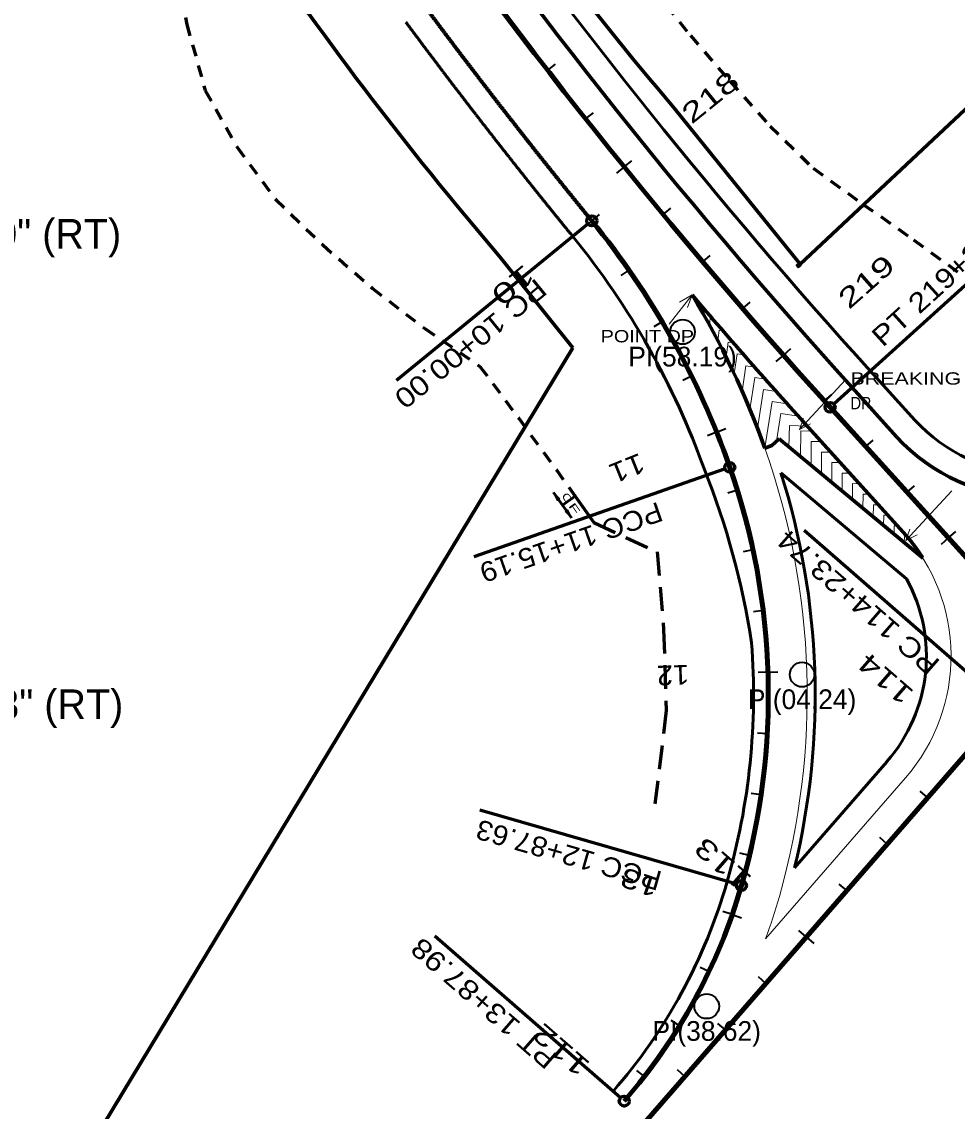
# Model space of a CAD drawing. Extents: x 2717836 to 2719883, y 337327 to 339813.
# Drawn here: x 2718674.4 to 2719054.1, y 337871.3 to 338313.3 of the extents above; entities that cross this region are included whole.
import ezdxf
from ezdxf.enums import TextEntityAlignment as Align

# ---------------------------------------------------------------- set-up
doc = ezdxf.new("R2010")
doc.units = 0
doc.header["$LTSCALE"] = 3.2
for name, pattern in [('LONG_DASHED', [7.5, 6, -1.5]), ('MEDIUM_DASHED', [4.5, 3, -1.5]), ('SHORT_DASHED', [2.7, 1.5, -1.2])]:
    doc.linetypes.add(name, pattern=pattern)
for name, color, linetype, lineweight in [('1', 7, 'Continuous', 106), ('2', 7, 'Continuous', 13), ('22', 7, 'SHORT_DASHED', 60), ('23', 7, 'Continuous', 70), ('24', 7, 'Continuous', 13), ('3', 7, 'Continuous', 70), ('31', 7, 'Continuous', 35), ('52', 7, 'Continuous', 53), ('6', 7, 'Continuous', 53), ('60', 7, 'Continuous', 13), ('61', 7, 'Continuous', 13), ('62', 7, 'Continuous', 13), ('8', 7, 'Continuous', 70)]:
    doc.layers.add(name, color=color, linetype=linetype, lineweight=lineweight)

msp = doc.modelspace()

# ---------------------------------------------------------------- hatches: boundary and pattern name
at = {"layer": '23'}
msp.add_hatch(color=256, dxfattribs=at).paths.add_polyline_path([(2718989.701, 338213.433), (2718988.659, 338214.512), (2718989.738, 338215.554), (2718990.78, 338214.474)])
at = {"layer": '52'}
for points in [[(2718890.257, 338122.283), (2718892.832, 338119.693), (2718891.815, 338120.076), (2718891.826, 338118.982)], [(2718897.478, 338112.08), (2718894.903, 338114.67), (2718895.92, 338114.288), (2718895.908, 338115.382)]]:
    msp.add_hatch(color=256, dxfattribs=at).paths.add_polyline_path(points)

# ---------------------------------------------------------------- linework, layer by layer
at = {"layer": '1'}
for p, q in [((2719002.473, 338156.897), (2719189.327, 337950.539)), ((2718598.813, 337489.479), (2719074.059, 338035.314))]:
    msp.add_line(p, q, dxfattribs=at)
for centre, radius, start, end in [((2720744.453, 339734.238), 2350, 206.79977, 222.16044), ((2718650.191, 338023.775), 330, 19.23982, 39.23982), ((2718697.399, 338040.251), 280, 343.95467, 19.23982), ((2718745.451, 338026.431), 230, 318.95467, 343.95467)]:
    msp.add_arc(centre, radius, start, end, dxfattribs=at)
at = {"layer": '2'}
msp.add_line((2719033.086, 338006.53), (2718976.223, 337941.221), dxfattribs=at)
for centre, radius, start, end in [((2718692.921, 338040.106), 300.266, 344.21749, 19.50264), ((2718976.549, 338055.909), 75, 318.86607, 42.16044), ((2718745.451, 338026.431), 246, 339.73408, 343.95467)]:
    msp.add_arc(centre, radius, start, end, dxfattribs=at)
at = {"layer": '22'}
for p, q in [((2718736.378, 338340.568), (2718741.398, 338312.243)), ((2718930.49, 338326.699), (2718945.807, 338307.673)), ((2718741.398, 338312.243), (2718748.912, 338285.405)), ((2718945.807, 338307.673), (2718961.775, 338289.179)), ((2718961.775, 338289.179), (2718978.102, 338271.004)), ((2718748.912, 338285.405), (2718761.889, 338262.366)), ((2718978.102, 338271.004), (2718995.614, 338253.858)), ((2718761.889, 338262.366), (2718777.485, 338241.226)), ((2718995.614, 338253.858), (2719015.923, 338239.196)), ((2718777.485, 338241.226), (2718796.55, 338222.768)), ((2718796.55, 338222.768), (2718816.646, 338205.231)), ((2718816.646, 338205.231), (2718837.975, 338188.825)), ((2718837.975, 338188.825), (2718860.375, 338173.479)), ((2718860.375, 338173.479), (2718875.971, 338152.581)), ((2718875.971, 338152.581), (2718891.404, 338131.497)), ((2718891.404, 338131.497), (2718898.972, 338120.794))]:
    msp.add_line(p, q, dxfattribs=at)
at = {"layer": '22', "linetype": 'LONG_DASHED'}
msp.add_line((2718898.972, 338120.794), (2718906.541, 338110.092), dxfattribs=at)
at = {"layer": '22', "linetype": 'MEDIUM_DASHED'}
msp.add_line((2718906.541, 338110.092), (2718932.305, 338098.2), dxfattribs=at)
at = {"layer": '22'}
msp.add_lwpolyline([(2719015.923, 338239.196), (2719036.374, 338224.824), (2719056.377, 338210.214)], dxfattribs=at)
at = {"layer": '22', "linetype": 'MEDIUM_DASHED'}
msp.add_lwpolyline([(2718932.305, 338098.2), (2718934.904, 338066.645), (2718935.99, 338033.903), (2718931.4, 337996.021)], dxfattribs=at)
at = {"layer": '23'}
for p, q in [((2719374.169, 338574.501), (2718990.259, 338215.014)), ((2718939.297, 338278.13), (2718990.259, 338215.014)), ((2718868.503, 338217.98), (2718898.006, 338180.983)), ((2718898.006, 338180.983), (2718492.996, 337510.896))]:
    msp.add_line(p, q, dxfattribs=at)
at = {"layer": '23', "lineweight": 25}
msp.add_lwpolyline([(2718989.701, 338213.433), (2718988.659, 338214.512), (2718989.738, 338215.554), (2718990.78, 338214.474)], close=True, dxfattribs=at)
at = {"layer": '23'}
for centre, radius, start, end in [((2718932.366, 337992.345), 585.751, 113.27176, 113.27176), ((2720030.046, 339206.574), 1432.39, 206.96023, 220.40436), ((2719954.557, 339151.911), 1432.39, 206.65897, 220.69325)]:
    msp.add_arc(centre, radius, start, end, dxfattribs=at)
at = {"layer": '24'}
for p, q in [((2718950.04, 338196.418), (2718950.2, 338197.65)), ((2718950.638, 338197.593), (2718950.2, 338197.65)), ((2718953.504, 338190.257), (2718953.855, 338192.891)), ((2718954.783, 338192.768), (2718953.855, 338192.891)), ((2718956.916, 338183.883), (2718957.494, 338188.121)), ((2718958.97, 338187.92), (2718957.494, 338188.121)), ((2718960.272, 338177.282), (2718961.118, 338183.339)), ((2718963.2, 338183.049), (2718961.118, 338183.339)), ((2718963.567, 338170.439), (2718964.726, 338178.545)), ((2718967.476, 338178.152), (2718964.726, 338178.545)), ((2718966.795, 338163.334), (2718968.318, 338173.739)), ((2718971.798, 338173.23), (2718968.318, 338173.739)), ((2718969.95, 338155.946), (2718971.894, 338168.921)), ((2718976.169, 338168.28), (2718971.894, 338168.921)), ((2718973.023, 338148.25), (2718975.452, 338164.09)), ((2718980.59, 338163.302), (2718975.452, 338164.09)), ((2718976.033, 338140.377), (2718978.993, 338159.247)), ((2718985.064, 338158.294), (2718978.993, 338159.247)), ((2718980.692, 338143.103), (2718982.517, 338154.39)), ((2718989.6, 338153.245), (2718982.517, 338154.39)), ((2718985.735, 338140.731), (2718986.042, 338149.536)), ((2718993.173, 338149.288), (2718986.042, 338149.536)), ((2718990.504, 338136.784), (2718990.6, 338147.307)), ((2718995.003, 338147.267), (2718990.6, 338147.307)), ((2718994.719, 338133.295), (2718994.805, 338143.027)), ((2718998.874, 338142.991), (2718994.805, 338143.027)), ((2718998.931, 338129.808), (2718999.01, 338138.747)), ((2719002.747, 338138.714), (2718999.01, 338138.747)), ((2719003.142, 338126.322), (2719003.215, 338134.467)), ((2719006.62, 338134.437), (2719003.215, 338134.467)), ((2719007.354, 338122.835), (2719007.42, 338130.187)), ((2719010.493, 338130.159), (2719007.42, 338130.187)), ((2719011.566, 338119.349), (2719011.624, 338125.907)), ((2719014.366, 338125.882), (2719011.624, 338125.907)), ((2719015.778, 338115.863), (2719015.829, 338121.626)), ((2719018.239, 338121.605), (2719015.829, 338121.626)), ((2719019.99, 338112.376), (2719020.034, 338117.346)), ((2719022.112, 338117.328), (2719020.034, 338117.346)), ((2719024.202, 338108.89), (2719024.239, 338113.066)), ((2719025.985, 338113.051), (2719024.239, 338113.066)), ((2719028.414, 338105.403), (2719028.444, 338108.786)), ((2719029.858, 338108.773), (2719028.444, 338108.786)), ((2719032.529, 338101.997), (2719032.64, 338104.498)), ((2719033.721, 338104.45), (2719032.64, 338104.498))]:
    msp.add_line(p, q, dxfattribs=at)
at = {"layer": '3'}
for p, q in [((2719011.368, 338164.951), (2719029.47, 338144.96)), ((2718975.96, 338140.349), (2718978.769, 338141.359)), ((2718981.734, 338144.044), (2718978.769, 338141.359))]:
    msp.add_line(p, q, dxfattribs=at)
at = {"layer": '3', "lineweight": 13}
msp.add_lwpolyline([(2718993.577, 338148.842), (2719031.255, 338107.232), (2719032.145, 338106.25)], dxfattribs=at)
at = {"layer": '3'}
msp.add_lwpolyline([(2718981.734, 338144.044), (2719039.155, 338096.513), (2719040.109, 338095.724)], dxfattribs=at)
for centre, radius, start, end in [((2720744.453, 339734.238), 2338, 206.79977, 222.16044), ((2718650.191, 338023.775), 330, 19.23982, 39.23982), ((2718650.191, 338023.775), 330, 19.23982, 39.23982), ((2719085.065, 338195.301), 75, 222.16044, 316.72468), ((2718697.399, 338040.251), 280, 343.95467, 19.23982), ((2718697.399, 338040.251), 280, 343.95467, 19.23982), ((2718745.451, 338026.431), 230, 318.95467, 343.95467), ((2718745.451, 338026.431), 230, 318.95467, 343.95467)]:
    msp.add_arc(centre, radius, start, end, dxfattribs=at)
at = {"layer": '3', "lineweight": 13}
for centre, radius, start, end in [((2718662.067, 338029.421), 332.917, 19.82595, 31.31675), ((2720759.569, 339747.514), 2382.117, 220.43651, 222.14825), ((2721152.646, 340103.725), 2912.583, 222.15462, 222.1586), ((2718640.384, 338021.681), 355.94, 19.4749, 19.81422)]:
    msp.add_arc(centre, radius, start, end, dxfattribs=at)
at = {"layer": '3'}
for points in [[(2718838.33, 338319.116), (2718838.769, 338318.524), (2718839.215, 338317.924), (2718839.655, 338317.332), (2718840.102, 338316.732), (2718840.542, 338316.141), (2718840.989, 338315.541), (2718841.429, 338314.95), (2718841.87, 338314.359), (2718842.318, 338313.76), (2718842.759, 338313.169), (2718843.207, 338312.57), (2718843.648, 338311.98), (2718844.09, 338311.39), (2718844.538, 338310.791), (2718844.981, 338310.201), (2718845.429, 338309.603), (2718845.872, 338309.013), (2718846.321, 338308.415), (2718846.764, 338307.826), (2718847.207, 338307.236), (2718847.656, 338306.639), (2718848.1, 338306.05), (2718848.55, 338305.453), (2718848.994, 338304.864), (2718849.438, 338304.275), (2718849.888, 338303.679), (2718850.333, 338303.09), (2718850.783, 338302.494), (2718851.228, 338301.906), (2718851.679, 338301.309), (2718852.124, 338300.722), (2718852.57, 338300.134), (2718853.022, 338299.538), (2718853.467, 338298.951), (2718853.919, 338298.355), (2718854.365, 338297.768), (2718854.818, 338297.173), (2718855.264, 338296.586), (2718855.711, 338295.999), (2718856.164, 338295.405), (2718856.611, 338294.818), (2718857.064, 338294.224), (2718857.512, 338293.637), (2718857.96, 338293.051), (2718858.413, 338292.457), (2718858.861, 338291.872), (2718859.316, 338291.278), (2718859.764, 338290.692), (2718860.219, 338290.099), (2718860.667, 338289.514), (2718861.116, 338288.929), (2718861.571, 338288.336), (2718862.021, 338287.751), (2718862.476, 338287.158), (2718862.926, 338286.574), (2718863.376, 338285.989), (2718863.832, 338285.397), (2718864.282, 338284.813), (2718864.738, 338284.221), (2718865.189, 338283.637), (2718865.646, 338283.045), (2718866.097, 338282.462), (2718866.548, 338281.878), (2718867.005, 338281.287), (2718867.457, 338280.704), (2718867.914, 338280.113), (2718868.366, 338279.53), (2718868.818, 338278.947), (2718869.277, 338278.357), (2718869.729, 338277.774), (2718870.188, 338277.184), (2718870.64, 338276.602), (2718871.099, 338276.012), (2718871.553, 338275.43)], [(2718871.553, 338275.43), (2718872.006, 338274.848), (2718872.465, 338274.259), (2718872.919, 338273.677), (2718873.379, 338273.088), (2718873.833, 338272.507), (2718874.293, 338271.918), (2718874.748, 338271.337), (2718875.202, 338270.756), (2718875.663, 338270.168), (2718876.118, 338269.587), (2718876.579, 338268.999), (2718877.035, 338268.419), (2718877.49, 338267.839), (2718877.952, 338267.251), (2718878.408, 338266.671), (2718878.87, 338266.084), (2718879.326, 338265.504), (2718879.789, 338264.917), (2718880.245, 338264.338), (2718880.702, 338263.759), (2718881.165, 338263.172), (2718881.622, 338262.593), (2718882.086, 338262.007), (2718882.543, 338261.428), (2718883.001, 338260.85), (2718883.465, 338260.264), (2718883.923, 338259.686), (2718884.387, 338259.1), (2718884.845, 338258.522), (2718885.31, 338257.937), (2718885.769, 338257.36), (2718886.228, 338256.782), (2718886.693, 338256.197), (2718887.152, 338255.62), (2718887.618, 338255.035), (2718888.078, 338254.459), (2718888.537, 338253.882), (2718889.004, 338253.298), (2718889.464, 338252.721), (2718889.93, 338252.137), (2718890.391, 338251.561), (2718890.858, 338250.978), (2718891.319, 338250.402), (2718891.78, 338249.826), (2718892.247, 338249.243), (2718892.709, 338248.668), (2718893.176, 338248.085), (2718893.638, 338247.51), (2718894.106, 338246.927), (2718894.569, 338246.352), (2718895.031, 338245.778), (2718895.5, 338245.195), (2718895.962, 338244.621), (2718896.431, 338244.039), (2718896.894, 338243.465), (2718897.358, 338242.891), (2718897.827, 338242.31), (2718898.291, 338241.736), (2718898.761, 338241.155), (2718899.225, 338240.581), (2718899.695, 338240), (2718900.16, 338239.427), (2718900.624, 338238.855), (2718901.095, 338238.274), (2718901.56, 338237.702), (2718902.031, 338237.121), (2718902.496, 338236.549), (2718902.962, 338235.977), (2718903.433, 338235.397), (2718903.899, 338234.825), (2718904.371, 338234.246), (2718904.837, 338233.674), (2718905.776, 338232.524)]]:
    msp.add_spline(points, degree=3, dxfattribs=at)
at = {"layer": '31'}
for p, q in [((2718887.829, 338293.596), (2718890.989, 338296.049)), ((2718903.26, 338273.927), (2718906.394, 338276.413)), ((2718918.899, 338254.423), (2718922.006, 338256.942)), ((2718918.899, 338254.423), (2718915.792, 338251.904)), ((2718905.778, 338232.522), (2718908.876, 338235.052)), ((2718934.745, 338235.086), (2718937.825, 338237.638)), ((2718905.778, 338232.522), (2718902.68, 338229.992)), ((2718950.795, 338215.919), (2718953.848, 338218.503)), ((2718920.844, 338212.579), (2718917.563, 338210.291)), ((2718967.049, 338196.924), (2718970.074, 338199.541)), ((2718934.357, 338191.553), (2718930.913, 338189.52)), ((2718983.503, 338178.103), (2718986.501, 338180.751)), ((2718983.503, 338178.103), (2718980.506, 338175.454)), ((2718946.241, 338169.565), (2718942.652, 338167.798)), ((2719000.157, 338159.458), (2719003.126, 338162.138)), ((2718956.426, 338146.74), (2718952.714, 338145.25)), ((2718956.426, 338146.74), (2718960.137, 338148.231)), ((2719016.936, 338140.924), (2719019.901, 338143.609)), ((2718964.829, 338123.202), (2718961.009, 338122.017)), ((2719033.716, 338122.392), (2719036.681, 338125.077)), ((2719050.496, 338103.861), (2719053.461, 338106.546)), ((2719050.496, 338103.861), (2719047.531, 338101.176)), ((2718971.16, 338099.026), (2718967.249, 338098.186)), ((2718975.311, 338074.381), (2718971.34, 338073.893)), ((2718977.247, 338049.464), (2718973.249, 338049.333)), ((2718977.247, 338049.464), (2718981.245, 338049.596)), ((2718976.954, 338024.474), (2718972.96, 338024.7)), ((2718974.433, 337999.61), (2718970.476, 338000.191)), ((2719042.056, 337998.557), (2719039.039, 338001.184)), ((2719025.639, 337979.703), (2719022.623, 337982.329)), ((2718969.706, 337975.07), (2718965.816, 337976.001)), ((2719009.223, 337960.848), (2719006.206, 337963.475)), ((2718962.753, 337951.067), (2718958.974, 337952.377)), ((2718962.753, 337951.067), (2718966.532, 337949.756)), ((2718992.807, 337941.993), (2718989.79, 337944.62)), ((2718992.807, 337941.993), (2718995.823, 337939.367)), ((2718953.295, 337927.938), (2718949.68, 337929.651)), ((2718976.39, 337923.138), (2718973.373, 337925.765)), ((2718941.384, 337905.972), (2718937.976, 337908.067)), ((2718959.974, 337904.284), (2718956.957, 337906.91)), ((2718927.16, 337885.428), (2718923.999, 337887.88)), ((2718943.557, 337885.429), (2718940.541, 337888.056))]:
    msp.add_line(p, q, dxfattribs=at)
at = {"layer": '31', "lineweight": 60}
for p, q in [((2718904.229, 338231.257), (2718826.462, 338167.741)), ((2719003.955, 338158.239), (2719083.848, 338230.581)), ((2718959.872, 338131.858), (2718857.934, 338096.28)), ((2719072.55, 338036.627), (2718991.882, 338106.863)), ((2718964.569, 337963.412), (2718860.262, 337993.411)), ((2718917.406, 337876.713), (2718842.011, 337942.358))]:
    msp.add_line(p, q, dxfattribs=at)
for centre in [(2718905.778, 338232.522), (2719002.473, 338156.897), (2718961.76, 338132.517), (2718966.491, 337962.86), (2718918.914, 337875.4)]:
    msp.add_circle(centre, 2, dxfattribs=at)
at = {"layer": '31'}
for centre in [(2718942.586, 338187.455), (2718991.104, 338048.441), (2718952.397, 337913.856)]:
    msp.add_circle(centre, 5, dxfattribs=at)
at = {"layer": '52'}
for p, q in [((2718890.257, 338122.283), (2718897.478, 338112.08)), ((2718893.867, 338117.182), (2718898.972, 338120.794))]:
    msp.add_line(p, q, dxfattribs=at)
at = {"layer": '52', "lineweight": 25}
for points in [[(2718890.257, 338122.283), (2718892.832, 338119.693), (2718891.815, 338120.076), (2718891.826, 338118.982)], [(2718897.478, 338112.08), (2718894.903, 338114.67), (2718895.92, 338114.288), (2718895.908, 338115.382)]]:
    msp.add_lwpolyline(points, close=True, dxfattribs=at)
at = {"layer": '6'}
for p, q in [((2719018.781, 338171.663), (2719036.882, 338151.672)), ((2718982.514, 338130.307), (2719033.495, 338087.249)), ((2718988.031, 337970.012), (2719025.544, 338013.097))]:
    msp.add_line(p, q, dxfattribs=at)
for centre, radius, start, end in [((2720744.453, 339734.238), 2328, 208.64257, 222.16044), ((2718650.191, 338023.775), 320, 19.68984, 39.23982), ((2719085.065, 338195.301), 65, 222.16044, 316.72468), ((2718654.256, 338013.029), 320, 8.68814, 21.747), ((2718697.399, 338040.251), 299, 346.41349, 17.52915), ((2718976.549, 338055.909), 65, 318.86607, 28.82624), ((2718697.399, 338040.251), 274, 343.95467, 4.41993), ((2718745.451, 338026.431), 224, 318.95467, 343.95467)]:
    msp.add_arc(centre, radius, start, end, dxfattribs=at)
for points in [[(2718830.301, 338313.154), (2718830.742, 338312.56), (2718831.19, 338311.958), (2718831.632, 338311.364), (2718832.08, 338310.761), (2718832.522, 338310.167), (2718832.971, 338309.565), (2718833.413, 338308.972), (2718833.856, 338308.378), (2718834.305, 338307.777), (2718834.748, 338307.183), (2718835.198, 338306.582), (2718835.641, 338305.989), (2718836.085, 338305.396), (2718836.535, 338304.795), (2718836.979, 338304.203), (2718837.43, 338303.602), (2718837.874, 338303.01), (2718838.325, 338302.409), (2718838.77, 338301.817), (2718839.215, 338301.225), (2718839.666, 338300.626), (2718840.112, 338300.034), (2718840.564, 338299.434), (2718841.009, 338298.843), (2718841.455, 338298.252), (2718841.908, 338297.653), (2718842.354, 338297.062), (2718842.807, 338296.463), (2718843.253, 338295.872), (2718843.706, 338295.274), (2718844.153, 338294.683), (2718844.601, 338294.093), (2718845.054, 338293.495), (2718845.502, 338292.905), (2718845.956, 338292.307), (2718846.404, 338291.717), (2718846.858, 338291.12), (2718847.307, 338290.53), (2718847.755, 338289.941), (2718848.21, 338289.344), (2718848.659, 338288.755), (2718849.114, 338288.158), (2718849.564, 338287.569), (2718850.013, 338286.981), (2718850.469, 338286.384), (2718850.919, 338285.796), (2718851.375, 338285.2), (2718851.825, 338284.612), (2718852.282, 338284.016), (2718852.732, 338283.428), (2718853.183, 338282.84), (2718853.64, 338282.245), (2718854.091, 338281.658), (2718854.549, 338281.063), (2718855, 338280.476), (2718855.452, 338279.889), (2718855.91, 338279.294), (2718856.362, 338278.707), (2718856.821, 338278.113), (2718857.273, 338277.527), (2718857.732, 338276.932), (2718858.185, 338276.346), (2718858.638, 338275.76), (2718859.097, 338275.167), (2718859.55, 338274.581), (2718860.01, 338273.988), (2718860.464, 338273.402), (2718860.918, 338272.817), (2718861.378, 338272.224), (2718861.832, 338271.639), (2718862.293, 338271.046), (2718862.747, 338270.462), (2718863.208, 338269.869), (2718863.662, 338269.286)], [(2718863.664, 338269.284), (2718864.119, 338268.701), (2718864.58, 338268.109), (2718865.036, 338267.525), (2718865.498, 338266.933), (2718865.953, 338266.35), (2718866.416, 338265.758), (2718866.872, 338265.175), (2718867.328, 338264.592), (2718867.791, 338264.001), (2718868.248, 338263.418), (2718868.711, 338262.827), (2718869.169, 338262.244), (2718869.626, 338261.662), (2718870.09, 338261.072), (2718870.547, 338260.49), (2718871.012, 338259.9), (2718871.47, 338259.318), (2718871.934, 338258.728), (2718872.393, 338258.146), (2718872.851, 338257.565), (2718873.316, 338256.976), (2718873.775, 338256.394), (2718874.241, 338255.805), (2718874.7, 338255.224), (2718875.16, 338254.644), (2718875.626, 338254.055), (2718876.086, 338253.475), (2718876.552, 338252.886), (2718877.012, 338252.306), (2718877.479, 338251.718), (2718877.94, 338251.138), (2718878.4, 338250.559), (2718878.868, 338249.971), (2718879.329, 338249.392), (2718879.796, 338248.804), (2718880.258, 338248.225), (2718880.72, 338247.646), (2718881.188, 338247.059), (2718881.65, 338246.481), (2718882.119, 338245.894), (2718882.581, 338245.316), (2718883.05, 338244.73), (2718883.513, 338244.151), (2718883.976, 338243.573), (2718884.445, 338242.988), (2718884.909, 338242.41), (2718885.378, 338241.824), (2718885.842, 338241.247), (2718886.312, 338240.662), (2718886.776, 338240.085), (2718887.241, 338239.508), (2718887.711, 338238.923), (2718888.176, 338238.346), (2718888.647, 338237.762), (2718889.112, 338237.185), (2718889.577, 338236.609), (2718890.049, 338236.025), (2718890.514, 338235.449), (2718890.986, 338234.865), (2718891.452, 338234.29), (2718891.925, 338233.706), (2718892.391, 338233.131), (2718892.857, 338232.556), (2718893.33, 338231.973), (2718893.797, 338231.398), (2718894.27, 338230.815), (2718894.737, 338230.24), (2718895.205, 338229.666), (2718895.679, 338229.084), (2718896.146, 338228.509), (2718896.62, 338227.927), (2718897.089, 338227.353), (2718898.029, 338226.201)]]:
    msp.add_spline(points, degree=3, dxfattribs=at)
at = {"layer": '60'}
msp.add_line((2719033.232, 338102.845), (2719034.862, 338107.376), dxfattribs=at)
msp.add_lwpolyline([(2719051.887, 338122.962), (2719033.232, 338102.845), (2719037.76, 338105.201)], dxfattribs=at)
at = {"layer": '61'}
msp.add_line((2718990.042, 338147.876), (2718994.569, 338150.232), dxfattribs=at)
msp.add_lwpolyline([(2719008.697, 338167.993), (2718990.042, 338147.876), (2718991.672, 338152.407)], dxfattribs=at)
at = {"layer": '62'}
for p in [(2718937.158, 338190.612), (2718941.324, 338199.492), (2718944.584, 338197.317)]:
    msp.add_line(p, (2718946.477, 338202.464), dxfattribs=at)
at = {"layer": '8'}
for p, q in [((2718993.575, 338148.843), (2719032.142, 338106.25)), ((2718975.957, 338140.35), (2718978.767, 338141.36)), ((2718981.732, 338144.045), (2718978.767, 338141.36)), ((2718981.732, 338144.045), (2719040.053, 338095.769))]:
    msp.add_line(p, q, dxfattribs=at)
for centre, radius, start, end in [((2720744.451, 339734.239), 2362, 220.42917, 222.16044), ((2718650.189, 338023.776), 346, 19.68926, 31.09375), ((2718976.547, 338055.91), 75, 32.50196, 42.16044)]:
    msp.add_arc(centre, radius, start, end, dxfattribs=at)

# ---------------------------------------------------------------- texts
at = {"layer": '31'}
for s, rotation, width, p in [('218', 39.029, 1.45, (2718946.276, 338271.466)), ('PT 219+28.45', 42.16, 1.2, (2719023.844, 338180.97)), ('219', 41.467, 1.45, (2719010.131, 338196.295)), ('10', 219.24, 1.55, (2718878.463, 338215.378)), ('PC 10+00.00', 219.24, 1.2, (2718883.208, 338209.569)), ('11', 201.877, 1.2, (2718925.24, 338138.528)), ('PCC 11+15.19', 199.24, 1.1, (2718932.701, 338118.668)), ('PC 114+23.74', 138.955, 1.2, (2719047.626, 338053.687)), ('114', 138.955, 1.4, (2719036.965, 338041.442)), ('12', 181.886, 1.1, (2718945.133, 338052.409)), ('PCC 12+87.63', 163.955, 1.1, (2718934.77, 337968.341)), ('113', 138.955, 1.45, (2718971.299, 337966.023)), ('13', 160.873, 1.3, (2718933.83, 337965.331)), ('PT 13+87.98', 138.955, 1.2, (2718892.482, 337893.773)), ('112', 138.955, 1.45, (2718905.634, 337890.604))]:
    msp.add_text(s, height=8, rotation=rotation, dxfattribs=dict(at, width=width)).set_placement(p)
for s, p in [('DELTA = 20° 00\' 00.00" (RT)', (2718508.303, 338221.273)), ('DELTA = 35° 17\' 06.53" (RT)', (2718509.144, 338030.42))]:
    msp.add_text(s, height=12, dxfattribs=at).set_placement(p)
for s, p in [('PI(58.19)', (2718942.587, 338173.455)), ('PI(04.24)', (2718991.104, 338034.441)), ('PI(38.62)', (2718952.397, 337899.856))]:
    msp.add_text(s, height=8, dxfattribs=at).set_placement(p, align=Align.CENTER)
at = {"layer": '52'}
for s, width, p in [('C', 1.45, (2718894.506, 338119.281)), ('F', 1.95, (2718897.451, 338114.924))]:
    msp.add_text(s, height=3, rotation=305.287, dxfattribs=dict(at, width=width)).set_placement(p, align=Align.CENTER)
at = {"layer": '61'}
for s, width, p in [('BREAKING LINE ', 1.3, (2719010.723, 338166.075)), ('DP', 0.9, (2719010.723, 338156.076))]:
    msp.add_text(s, height=5, dxfattribs=dict(at, width=width)).set_placement(p)
at = {"layer": '62', "width": 1.2}
msp.add_text('POINT DP', height=5, dxfattribs=at).set_placement((2718909.37, 338183.235))

doc.saveas('drawing.dxf')
